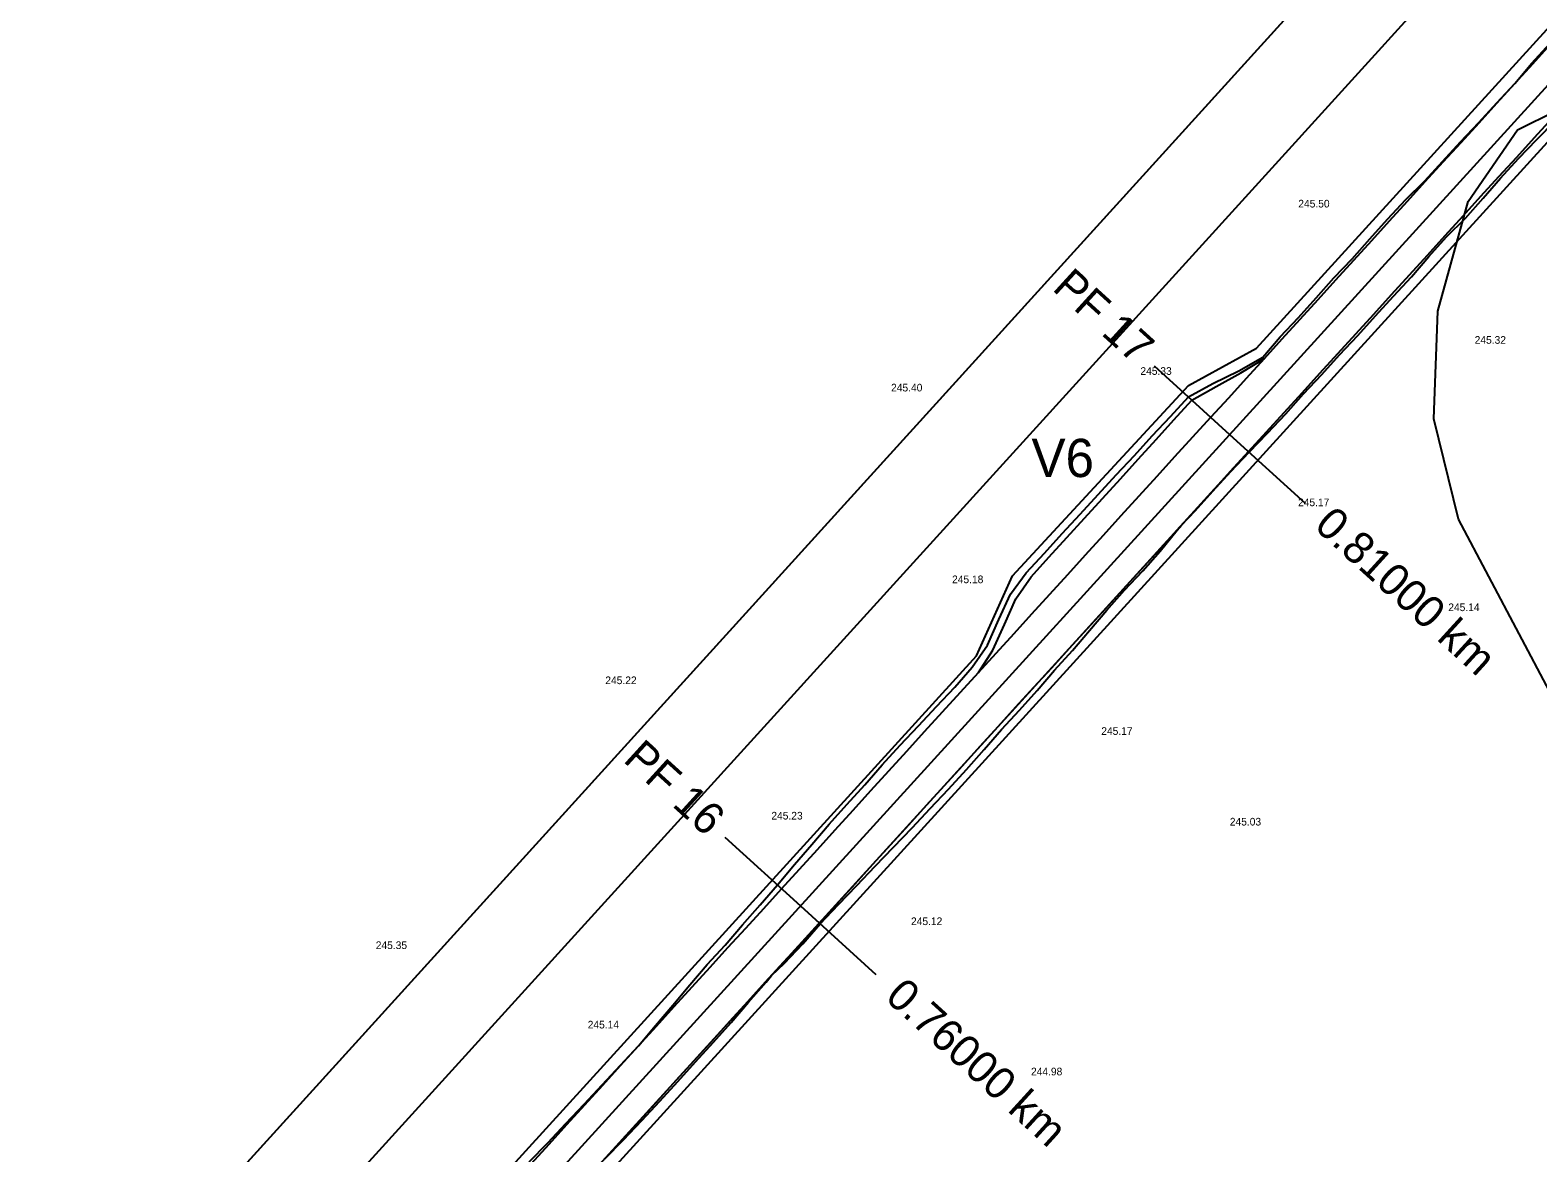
# Model space of a CAD drawing. Extents: x -555887 to -552101, y -1100251 to -1096546.
# Drawn here: x -554433.8 to -554315.6, y -1097049.5 to -1096961.4 of the extents above; entities that cross this region are included whole.
import ezdxf

# ---------------------------------------------------------------- set-up
doc = ezdxf.new("R2010")
doc.units = 0
for name, color, linetype in [('IP_návrh', 7, 'Continuous'), ('PARCELY_cesty', 7, 'Continuous'), ('POLYGONY_POPIS_CESTY', 7, 'Continuous'), ('POLYGONY_SITUACE_PF', 7, 'Continuous'), ('POLYGONY_SITUACE_PF_POPISY', 7, 'Continuous'), ('POLYGONY_SITUACE_PO', 7, 'Continuous'), ('vrstevnice', 7, 'Continuous'), ('Výškopis', 7, 'Continuous'), ('zájem', 7, 'Continuous')]:
    doc.layers.add(name, color=color, linetype=linetype)

msp = doc.modelspace()

# ---------------------------------------------------------------- linework, layer by layer
at = {"layer": 'IP_návrh'}
msp.add_line((-554875.9, -1097565.92), (-554275.99, -1096905.69), dxfattribs=at)
at = {"layer": 'PARCELY_cesty'}
for points in [[(-554879.07, -1097590.15), (-554550.67, -1097229.32), (-554531.76, -1097208.54), (-554275.81, -1096927.3), (-554273.04, -1096923.94), (-554268.63, -1096916.51), (-554265.12, -1096907.97), (-554264.18, -1096901.52)], [(-554875.85, -1097577.71), (-554629.16, -1097306.65), (-554626.42, -1097299.8), (-554612.94, -1097285.13), (-554606.19, -1097281.41), (-554359.61, -1097010.48), (-554356.78, -1097004.21), (-554343, -1096989.28), (-554337.66, -1096986.36), (-554280.34, -1096923.38), (-554277.96, -1096920.48), (-554274.11, -1096913.98), (-554271.59, -1096906.68), (-554270.35, -1096901.41)]]:
    msp.add_lwpolyline(points, dxfattribs=at)
at = {"layer": 'POLYGONY_SITUACE_PF'}
for p, q in [((-554345.68, -1096987.74), (-554339.77, -1096993.12)), ((-554339.77, -1096993.12), (-554333.85, -1096998.51)), ((-554379.34, -1097024.72), (-554373.42, -1097030.1)), ((-554373.42, -1097030.1), (-554367.5, -1097035.49))]:
    msp.add_line(p, q, dxfattribs=at)
at = {"layer": 'POLYGONY_SITUACE_PO'}
for p, q in [((-554884.96, -1097592.18), (-554278.08, -1096925.34)), ((-554316.06, -1096963.99), (-554314.66, -1096962.45)), ((-554316, -1096964.04), (-554314.6, -1096962.5)), ((-554316, -1096964.04), (-554314.6, -1096962.5)), ((-554317.41, -1096965.59), (-554316.06, -1096963.99)), ((-554317.41, -1096965.59), (-554316, -1096964.04)), ((-554317.41, -1096965.59), (-554316, -1096964.04)), ((-554318.81, -1096967.12), (-554317.41, -1096965.59)), ((-554318.81, -1096967.13), (-554317.41, -1096965.59)), ((-554318.81, -1096967.13), (-554317.41, -1096965.59)), ((-554317.41, -1096965.59), (-554317.41, -1096965.59)), ((-554317.41, -1096965.59), (-554317.41, -1096965.59)), ((-554320.23, -1096968.65), (-554318.81, -1096967.12)), ((-554320.21, -1096968.67), (-554318.81, -1096967.13)), ((-554320.21, -1096968.67), (-554318.81, -1096967.13)), ((-554315.85, -1096969.82), (-554314.45, -1096968.28)), ((-554315.85, -1096969.82), (-554314.45, -1096968.28)), ((-554321.65, -1096970.17), (-554320.23, -1096968.65)), ((-554321.61, -1096970.21), (-554320.21, -1096968.67)), ((-554321.61, -1096970.21), (-554320.21, -1096968.67)), ((-554315.67, -1096969.98), (-554314.21, -1096968.5)), ((-554323.07, -1096971.7), (-554321.65, -1096970.17)), ((-554323.02, -1096971.75), (-554321.61, -1096970.21)), ((-554323.02, -1096971.75), (-554321.61, -1096970.21)), ((-554317.25, -1096971.36), (-554315.85, -1096969.82)), ((-554317.25, -1096971.36), (-554315.85, -1096969.82)), ((-554317.12, -1096971.48), (-554315.67, -1096969.98)), ((-554324.47, -1096973.24), (-554323.07, -1096971.7)), ((-554324.42, -1096973.29), (-554323.02, -1096971.75)), ((-554324.42, -1096973.29), (-554323.02, -1096971.75)), ((-554318.65, -1096972.9), (-554317.25, -1096971.36)), ((-554318.65, -1096972.9), (-554317.25, -1096971.36)), ((-554318.52, -1096973.02), (-554317.12, -1096971.48)), ((-554320.06, -1096974.44), (-554318.65, -1096972.9)), ((-554320.06, -1096974.44), (-554318.65, -1096972.9)), ((-554319.89, -1096974.59), (-554318.52, -1096973.02)), ((-554325.96, -1096974.7), (-554324.47, -1096973.24)), ((-554325.82, -1096974.83), (-554324.42, -1096973.29)), ((-554325.82, -1096974.83), (-554324.42, -1096973.29)), ((-554327.38, -1096976.23), (-554325.96, -1096974.7)), ((-554327.22, -1096976.37), (-554325.82, -1096974.83)), ((-554327.22, -1096976.37), (-554325.82, -1096974.83)), ((-554321.46, -1096975.98), (-554320.06, -1096974.44)), ((-554321.46, -1096975.98), (-554320.06, -1096974.44)), ((-554321.28, -1096976.15), (-554319.89, -1096974.59)), ((-554328.77, -1096977.78), (-554327.38, -1096976.23)), ((-554328.62, -1096977.91), (-554327.22, -1096976.37)), ((-554328.62, -1096977.91), (-554327.22, -1096976.37)), ((-554322.86, -1096977.52), (-554321.46, -1096975.98)), ((-554322.86, -1096977.52), (-554321.46, -1096975.98)), ((-554322.75, -1096977.62), (-554321.28, -1096976.15)), ((-554330.15, -1096979.34), (-554328.77, -1096977.78)), ((-554330.03, -1096979.45), (-554328.62, -1096977.91)), ((-554330.03, -1096979.45), (-554328.62, -1096977.91)), ((-554324.26, -1096979.06), (-554322.86, -1096977.52)), ((-554324.26, -1096979.06), (-554322.86, -1096977.52)), ((-554324.15, -1096979.17), (-554322.75, -1096977.62)), ((-554325.67, -1096980.6), (-554324.26, -1096979.06)), ((-554325.67, -1096980.6), (-554324.26, -1096979.06)), ((-554331.59, -1096980.85), (-554330.15, -1096979.34)), ((-554331.43, -1096980.99), (-554330.03, -1096979.45)), ((-554331.43, -1096980.99), (-554330.03, -1096979.45)), ((-554325.51, -1096980.75), (-554324.15, -1096979.17)), ((-554332.98, -1096982.4), (-554331.59, -1096980.85)), ((-554332.83, -1096982.53), (-554331.43, -1096980.99)), ((-554332.83, -1096982.53), (-554331.43, -1096980.99)), ((-554327.07, -1096982.14), (-554325.67, -1096980.6)), ((-554327.07, -1096982.14), (-554325.67, -1096980.6)), ((-554326.92, -1096982.28), (-554325.51, -1096980.75)), ((-554334.37, -1096983.95), (-554332.98, -1096982.4)), ((-554334.23, -1096984.07), (-554332.83, -1096982.53)), ((-554334.23, -1096984.07), (-554332.83, -1096982.53)), ((-554328.47, -1096983.69), (-554327.07, -1096982.14)), ((-554328.47, -1096983.69), (-554327.07, -1096982.14)), ((-554328.32, -1096983.82), (-554326.92, -1096982.28)), ((-554329.87, -1096985.23), (-554328.47, -1096983.69)), ((-554329.87, -1096985.23), (-554328.47, -1096983.69)), ((-554329.71, -1096985.37), (-554328.32, -1096983.82)), ((-554335.79, -1096985.47), (-554334.37, -1096983.95)), ((-554335.64, -1096985.62), (-554334.23, -1096984.07)), ((-554335.64, -1096985.62), (-554334.23, -1096984.07)), ((-554337.15, -1096987.05), (-554335.79, -1096985.47)), ((-554337.04, -1096987.16), (-554335.64, -1096985.62)), ((-554337.04, -1096987.16), (-554335.64, -1096985.62)), ((-554331.27, -1096986.77), (-554329.87, -1096985.23)), ((-554331.27, -1096986.77), (-554329.87, -1096985.23)), ((-554331.14, -1096986.89), (-554329.71, -1096985.37)), ((-554339.05, -1096988.14), (-554337.15, -1096987.05)), ((-554338.89, -1096988.29), (-554337.04, -1096987.16)), ((-554338.44, -1096988.7), (-554337.04, -1096987.16)), ((-554332.68, -1096988.31), (-554331.27, -1096986.77)), ((-554332.68, -1096988.31), (-554331.27, -1096986.77)), ((-554332.54, -1096988.43), (-554331.14, -1096986.89)), ((-554341.07, -1096989.12), (-554339.05, -1096988.14)), ((-554340.81, -1096989.36), (-554338.89, -1096988.29)), ((-554334.08, -1096989.85), (-554332.68, -1096988.31)), ((-554334.08, -1096989.85), (-554332.68, -1096988.31)), ((-554333.98, -1096989.94), (-554332.54, -1096988.43)), ((-554343, -1096990.18), (-554341.07, -1096989.12)), ((-554342.72, -1096990.43), (-554340.81, -1096989.36)), ((-554339.84, -1096990.24), (-554338.44, -1096988.7)), ((-554344.41, -1096991.71), (-554343, -1096990.18)), ((-554344.13, -1096991.97), (-554342.72, -1096990.43)), ((-554341.24, -1096991.78), (-554339.84, -1096990.24)), ((-554335.48, -1096991.39), (-554334.08, -1096989.85)), ((-554335.48, -1096991.39), (-554334.08, -1096989.85)), ((-554335.36, -1096991.5), (-554333.98, -1096989.94)), ((-554345.83, -1096993.24), (-554344.41, -1096991.71)), ((-554345.53, -1096993.51), (-554344.13, -1096991.97)), ((-554342.65, -1096993.32), (-554341.24, -1096991.78)), ((-554336.88, -1096992.93), (-554335.48, -1096991.39)), ((-554336.88, -1096992.93), (-554335.48, -1096991.39)), ((-554336.79, -1096993.01), (-554335.36, -1096991.5)), ((-554347.23, -1096994.78), (-554345.83, -1096993.24)), ((-554338.29, -1096994.47), (-554336.88, -1096992.93)), ((-554338.29, -1096994.47), (-554336.88, -1096992.93)), ((-554338.23, -1096994.52), (-554336.79, -1096993.01)), ((-554878.71, -1097588.28), (-554338.29, -1096994.47)), ((-554346.93, -1096995.05), (-554345.53, -1096993.51)), ((-554344.05, -1096994.86), (-554342.65, -1096993.32)), ((-554339.69, -1096996.01), (-554338.29, -1096994.47)), ((-554348.66, -1096996.29), (-554347.23, -1096994.78)), ((-554348.33, -1096996.6), (-554346.93, -1096995.05)), ((-554345.45, -1096996.4), (-554344.05, -1096994.86)), ((-554339.68, -1096996.02), (-554338.23, -1096994.52)), ((-554350.07, -1096997.83), (-554348.66, -1096996.29)), ((-554349.73, -1096998.14), (-554348.33, -1096996.6)), ((-554346.85, -1096997.94), (-554345.45, -1096996.4)), ((-554341.09, -1096997.55), (-554339.69, -1096996.01)), ((-554341.07, -1096997.58), (-554339.68, -1096996.02)), ((-554351.48, -1096999.37), (-554350.07, -1096997.83)), ((-554348.26, -1096999.48), (-554346.85, -1096997.94)), ((-554342.49, -1096999.09), (-554341.09, -1096997.55)), ((-554342.47, -1096999.11), (-554341.07, -1096997.58)), ((-554351.14, -1096999.68), (-554349.73, -1096998.14)), ((-554343.9, -1097000.63), (-554342.49, -1096999.09)), ((-554343.53, -1097000.23), (-554342.47, -1096999.11)), ((-554352.89, -1097000.9), (-554351.48, -1096999.37)), ((-554352.54, -1097001.22), (-554351.14, -1096999.68)), ((-554349.66, -1097001.02), (-554348.26, -1096999.48)), ((-554343.89, -1097000.64), (-554343.53, -1097000.23)), ((-554354.29, -1097002.44), (-554352.89, -1097000.9)), ((-554353.94, -1097002.76), (-554352.54, -1097001.22)), ((-554351.06, -1097002.56), (-554349.66, -1097001.02)), ((-554345.3, -1097002.17), (-554343.9, -1097000.63)), ((-554345.2, -1097002.27), (-554343.89, -1097000.64)), ((-554355.71, -1097003.97), (-554354.29, -1097002.44)), ((-554352.46, -1097004.1), (-554351.06, -1097002.56)), ((-554346.7, -1097003.72), (-554345.3, -1097002.17)), ((-554346.58, -1097003.82), (-554345.2, -1097002.27)), ((-554355.34, -1097004.3), (-554353.94, -1097002.76)), ((-554348.1, -1097005.26), (-554346.7, -1097003.72)), ((-554348, -1097005.35), (-554346.58, -1097003.82)), ((-554356.94, -1097005.66), (-554355.71, -1097003.97)), ((-554356.54, -1097006.03), (-554355.34, -1097004.3)), ((-554353.86, -1097005.65), (-554352.46, -1097004.1)), ((-554357.85, -1097007.65), (-554356.94, -1097005.66)), ((-554357.43, -1097008.04), (-554356.54, -1097006.03)), ((-554355.27, -1097007.19), (-554353.86, -1097005.65)), ((-554349.5, -1097006.8), (-554348.1, -1097005.26)), ((-554349.39, -1097006.9), (-554348, -1097005.35)), ((-554356.67, -1097008.73), (-554355.27, -1097007.19)), ((-554350.91, -1097008.34), (-554349.5, -1097006.8)), ((-554350.74, -1097008.49), (-554349.39, -1097006.9)), ((-554358.76, -1097009.64), (-554357.85, -1097007.65)), ((-554358.32, -1097010.04), (-554357.43, -1097008.04)), ((-554352.31, -1097009.88), (-554350.91, -1097008.34)), ((-554352.09, -1097010.08), (-554350.74, -1097008.49)), ((-554359.95, -1097011.38), (-554358.76, -1097009.64)), ((-554358.07, -1097010.27), (-554356.67, -1097008.73)), ((-554359.47, -1097011.81), (-554358.32, -1097010.04)), ((-554359.47, -1097011.81), (-554358.07, -1097010.27)), ((-554353.71, -1097011.42), (-554352.31, -1097009.88)), ((-554353.49, -1097011.62), (-554352.09, -1097010.08)), ((-554361.31, -1097012.95), (-554359.95, -1097011.38)), ((-554360.88, -1097013.35), (-554359.47, -1097011.81)), ((-554360.88, -1097013.35), (-554359.47, -1097011.81)), ((-554355.11, -1097012.96), (-554353.71, -1097011.42)), ((-554354.85, -1097013.2), (-554353.49, -1097011.62)), ((-554362.75, -1097014.46), (-554361.31, -1097012.95)), ((-554362.28, -1097014.89), (-554360.88, -1097013.35)), ((-554362.28, -1097014.89), (-554360.88, -1097013.35)), ((-554356.52, -1097014.5), (-554355.11, -1097012.96)), ((-554356.23, -1097014.76), (-554354.85, -1097013.2)), ((-554364.17, -1097015.98), (-554362.75, -1097014.46)), ((-554357.92, -1097016.04), (-554356.52, -1097014.5)), ((-554363.68, -1097016.43), (-554362.28, -1097014.89)), ((-554363.68, -1097016.43), (-554362.28, -1097014.89)), ((-554357.65, -1097016.28), (-554356.23, -1097014.76)), ((-554365.59, -1097017.51), (-554364.17, -1097015.98)), ((-554365.08, -1097017.97), (-554363.68, -1097016.43)), ((-554365.08, -1097017.97), (-554363.68, -1097016.43)), ((-554359.32, -1097017.58), (-554357.92, -1097016.04)), ((-554359.02, -1097017.85), (-554357.65, -1097016.28)), ((-554367, -1097019.05), (-554365.59, -1097017.51)), ((-554366.49, -1097019.51), (-554365.08, -1097017.97)), ((-554366.49, -1097019.51), (-554365.08, -1097017.97)), ((-554360.72, -1097019.12), (-554359.32, -1097017.58)), ((-554360.41, -1097019.41), (-554359.02, -1097017.85)), ((-554368.38, -1097020.6), (-554367, -1097019.05)), ((-554362.12, -1097020.66), (-554360.72, -1097019.12)), ((-554367.89, -1097021.05), (-554366.49, -1097019.51)), ((-554367.89, -1097021.05), (-554366.49, -1097019.51)), ((-554361.82, -1097020.94), (-554360.41, -1097019.41)), ((-554369.78, -1097022.15), (-554368.38, -1097020.6)), ((-554369.29, -1097022.59), (-554367.89, -1097021.05)), ((-554369.29, -1097022.59), (-554367.89, -1097021.05)), ((-554363.53, -1097022.2), (-554362.12, -1097020.66)), ((-554363.24, -1097022.46), (-554361.82, -1097020.94)), ((-554371.17, -1097023.7), (-554369.78, -1097022.15)), ((-554370.69, -1097024.13), (-554369.29, -1097022.59)), ((-554370.69, -1097024.13), (-554369.29, -1097022.59)), ((-554364.93, -1097023.75), (-554363.53, -1097022.2)), ((-554364.66, -1097023.99), (-554363.24, -1097022.46)), ((-554372.53, -1097025.28), (-554371.17, -1097023.7)), ((-554366.33, -1097025.29), (-554364.93, -1097023.75)), ((-554366.11, -1097025.49), (-554364.66, -1097023.99)), ((-554372.09, -1097025.68), (-554370.69, -1097024.13)), ((-554372.09, -1097025.68), (-554370.69, -1097024.13)), ((-554373.88, -1097026.86), (-554372.53, -1097025.28)), ((-554373.5, -1097027.22), (-554372.09, -1097025.68)), ((-554373.5, -1097027.22), (-554372.09, -1097025.68)), ((-554367.73, -1097026.83), (-554366.33, -1097025.29)), ((-554367.55, -1097027), (-554366.11, -1097025.49)), ((-554375.23, -1097028.46), (-554373.88, -1097026.86)), ((-554374.9, -1097028.76), (-554373.5, -1097027.22)), ((-554374.9, -1097028.76), (-554373.5, -1097027.22)), ((-554369.14, -1097028.37), (-554367.73, -1097026.83)), ((-554369, -1097028.5), (-554367.55, -1097027)), ((-554376.59, -1097030.03), (-554375.23, -1097028.46)), ((-554376.3, -1097030.3), (-554374.9, -1097028.76)), ((-554376.3, -1097030.3), (-554374.9, -1097028.76)), ((-554370.54, -1097029.91), (-554369.14, -1097028.37)), ((-554370.44, -1097030), (-554369, -1097028.5)), ((-554371.94, -1097031.45), (-554370.54, -1097029.91)), ((-554377.96, -1097031.6), (-554376.59, -1097030.03)), ((-554377.7, -1097031.84), (-554376.3, -1097030.3)), ((-554377.7, -1097031.84), (-554376.3, -1097030.3)), ((-554371.86, -1097031.52), (-554370.44, -1097030)), ((-554379.33, -1097033.18), (-554377.96, -1097031.6)), ((-554379.11, -1097033.38), (-554377.7, -1097031.84)), ((-554379.11, -1097033.38), (-554377.7, -1097031.84)), ((-554373.34, -1097032.99), (-554371.94, -1097031.45)), ((-554373.24, -1097033.09), (-554371.86, -1097031.52)), ((-554380.74, -1097034.71), (-554379.33, -1097033.18)), ((-554380.51, -1097034.92), (-554379.11, -1097033.38)), ((-554380.51, -1097034.92), (-554379.11, -1097033.38)), ((-554374.74, -1097034.53), (-554373.34, -1097032.99)), ((-554374.68, -1097034.59), (-554373.24, -1097033.09)), ((-554376.15, -1097036.07), (-554374.74, -1097034.53)), ((-554375.68, -1097035.56), (-554374.68, -1097034.59)), ((-554382.09, -1097036.3), (-554380.74, -1097034.71)), ((-554381.91, -1097036.46), (-554380.51, -1097034.92)), ((-554381.91, -1097036.46), (-554380.51, -1097034.92)), ((-554376.11, -1097036.1), (-554375.68, -1097035.56)), ((-554383.43, -1097037.89), (-554382.09, -1097036.3)), ((-554383.31, -1097038), (-554381.91, -1097036.46)), ((-554383.31, -1097038), (-554381.91, -1097036.46)), ((-554377.55, -1097037.61), (-554376.15, -1097036.07)), ((-554377.49, -1097037.67), (-554376.11, -1097036.1)), ((-554384.78, -1097039.48), (-554383.43, -1097037.89)), ((-554384.71, -1097039.54), (-554383.31, -1097038)), ((-554384.71, -1097039.54), (-554383.31, -1097038)), ((-554378.95, -1097039.15), (-554377.55, -1097037.61)), ((-554378.85, -1097039.24), (-554377.49, -1097037.67)), ((-554380.35, -1097040.69), (-554378.95, -1097039.15)), ((-554380.24, -1097040.79), (-554378.85, -1097039.24)), ((-554386.13, -1097041.07), (-554384.78, -1097039.48)), ((-554386.12, -1097041.08), (-554384.71, -1097039.54)), ((-554386.12, -1097041.08), (-554384.71, -1097039.54)), ((-554387.54, -1097042.6), (-554386.13, -1097041.07)), ((-554387.52, -1097042.62), (-554386.12, -1097041.08)), ((-554387.52, -1097042.62), (-554386.12, -1097041.08)), ((-554381.76, -1097042.23), (-554380.35, -1097040.69)), ((-554381.64, -1097042.34), (-554380.24, -1097040.79)), ((-554388.96, -1097044.13), (-554387.54, -1097042.6)), ((-554388.92, -1097044.16), (-554387.52, -1097042.62)), ((-554388.92, -1097044.16), (-554387.52, -1097042.62)), ((-554383.16, -1097043.78), (-554381.76, -1097042.23)), ((-554383.04, -1097043.88), (-554381.64, -1097042.34)), ((-554384.56, -1097045.32), (-554383.16, -1097043.78)), ((-554384.44, -1097045.43), (-554383.04, -1097043.88)), ((-554390.38, -1097045.65), (-554388.96, -1097044.13)), ((-554390.32, -1097045.71), (-554388.92, -1097044.16)), ((-554390.32, -1097045.71), (-554388.92, -1097044.16)), ((-554391.81, -1097047.17), (-554390.38, -1097045.65)), ((-554391.73, -1097047.25), (-554390.32, -1097045.71)), ((-554391.73, -1097047.25), (-554390.32, -1097045.71)), ((-554385.96, -1097046.86), (-554384.56, -1097045.32)), ((-554385.86, -1097046.95), (-554384.44, -1097045.43)), ((-554393.24, -1097048.68), (-554391.81, -1097047.17)), ((-554393.13, -1097048.79), (-554391.73, -1097047.25)), ((-554393.13, -1097048.79), (-554391.73, -1097047.25)), ((-554387.37, -1097048.4), (-554385.96, -1097046.86)), ((-554387.3, -1097048.46), (-554385.86, -1097046.95)), ((-554394.68, -1097050.19), (-554393.24, -1097048.68)), ((-554394.53, -1097050.33), (-554393.13, -1097048.79)), ((-554394.53, -1097050.33), (-554393.13, -1097048.79)), ((-554388.77, -1097049.94), (-554387.37, -1097048.4)), ((-554388.76, -1097049.94), (-554387.3, -1097048.46))]:
    msp.add_line(p, q, dxfattribs=at)
at = {"layer": 'vrstevnice'}
msp.add_lwpolyline([(-554314.68, -1097013.26), (-554321.81, -1096999.77), (-554323.74, -1096991.91), (-554323.44, -1096983.46), (-554321.06, -1096974.86), (-554317.19, -1096969.22), (-554311.07, -1096966.19)], dxfattribs=at)
at = {"layer": 'zájem'}
for points in [[(-554089.18, -1096729.49), (-554110.69, -1096747.36), (-554142.08, -1096773.53), (-554179.17, -1096807.62), (-554205.78, -1096822.41), (-554208.2, -1096823.7), (-554225.08, -1096837.14), (-554235.5, -1096849), (-554251.97, -1096867.91), (-554264.55, -1096882.42), (-554265.7, -1096883.76), (-554272.88, -1096891.67), (-554281.79, -1096901.5), (-554289.93, -1096910.44), (-554329.92, -1096954.43), (-554333.96, -1096958.92), (-554536.43, -1097182.04)], [(-554536.43, -1097182.04), (-554333.96, -1096958.92), (-554329.92, -1096954.43), (-554289.93, -1096910.44), (-554281.79, -1096901.5), (-554272.88, -1096891.67), (-554265.7, -1096883.76), (-554264.55, -1096882.42), (-554251.97, -1096867.91), (-554235.5, -1096849), (-554225.08, -1096837.14), (-554208.2, -1096823.7), (-554205.78, -1096822.41), (-554179.17, -1096807.62), (-554142.08, -1096773.53), (-554110.69, -1096747.36), (-554089.18, -1096729.49)]]:
    msp.add_lwpolyline(points, dxfattribs=at)

# ---------------------------------------------------------------- texts
at = {"layer": 'POLYGONY_POPIS_CESTY'}
msp.add_text('V6', height=3, rotation=359.8934, dxfattribs=at).set_placement((-554355.31, -1096996.46))
at = {"layer": 'POLYGONY_SITUACE_PF_POPISY'}
for s, p in [('PF 17', (-554353.75, -1096981.75)), ('0.81000 km', (-554333.23, -1097000.43)), ('PF 16', (-554387.4, -1097018.73)), ('0.76000 km', (-554366.88, -1097037.41))]:
    msp.add_text(s, height=2.5, rotation=317.6947, dxfattribs=at).set_placement(p)
at = {"layer": 'Výškopis'}
for s, p in [('245.50', (-554334.38, -1096975.32)), ('245.32', (-554320.55, -1096986.01)), ('245.33', (-554346.76, -1096988.45)), ('245.40', (-554366.31, -1096989.75)), ('245.17', (-554334.4, -1096998.75)), ('245.18', (-554361.53, -1097004.79)), ('245.14', (-554322.62, -1097006.98)), ('245.22', (-554388.72, -1097012.71)), ('245.17', (-554349.83, -1097016.69)), ('245.23', (-554375.7, -1097023.33)), ('245.03', (-554339.75, -1097023.8)), ('245.12', (-554364.75, -1097031.61)), ('245.35', (-554406.72, -1097033.49)), ('245.14', (-554390.1, -1097039.72)), ('244.98', (-554355.34, -1097043.4))]:
    msp.add_text(s, height=0.6, dxfattribs=at).set_placement(p)

doc.saveas('drawing.dxf')
